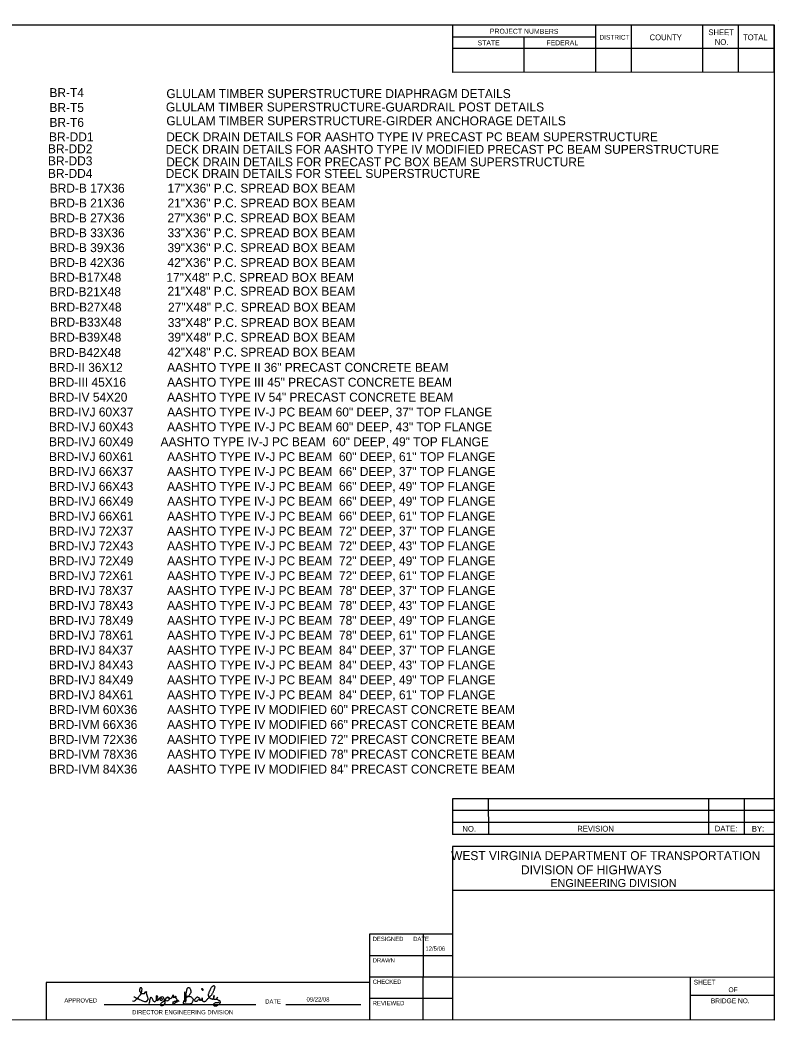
# Model space of a CAD drawing. Extents: x 4153 to 4683, y -1003 to -666.
# Drawn here: x 4427.6 to 4682.7, y -1002.2 to -666.2 of the extents above; entities that cross this region are included whole.
import ezdxf

# ---------------------------------------------------------------- set-up
doc = ezdxf.new("R2010")
doc.units = 0
for name, color, linetype in [('14', 7, 'Continuous'), ('63', 7, 'Continuous'), ('Level 1', 7, 'Continuous'), ('Level 14', 7, 'Continuous'), ('text', 7, 'Continuous')]:
    doc.layers.add(name, color=color, linetype=linetype)

msp = doc.modelspace()

# ---------------------------------------------------------------- linework, layer by layer
at = {"layer": '14'}
for p, q in [((4177.1, -667.82), (4681.11, -667.84)), ((4573.11, -683.83), (4573.11, -667.82)), ((4621.1, -683.82), (4621.11, -667.82)), ((4633.1, -683.82), (4633.11, -667.82)), ((4657.11, -683.82), (4657.11, -667.84)), ((4669.1, -683.82), (4669.11, -667.84)), ((4681.11, -667.84), (4681.1, -1002.24)), ((4681.11, -683.82), (4681.11, -667.84)), ((4621.11, -672.03), (4573.11, -672.03)), ((4597.11, -683.82), (4597.11, -672.03)), ((4681.1, -675.84), (4573.11, -675.82)), ((4681.11, -683.82), (4573.11, -683.83)), ((4681.03, -927.92), (4573.01, -927.91)), ((4573.03, -927.91), (4573.03, -939.91)), ((4585.01, -927.91), (4585.03, -939.9)), ((4659.01, -927.9), (4659.03, -939.9)), ((4671.03, -927.9), (4671.03, -939.9)), ((4681.03, -931.9), (4573.03, -931.9)), ((4681.03, -935.92), (4573.01, -935.91)), ((4681.01, -939.9), (4573.03, -939.91)), ((4573.03, -943.9), (4573.02, -1002.24)), ((4681.03, -943.92), (4573.03, -943.9)), ((4681.02, -958.73), (4573.02, -958.73)), ((4573.05, -973.43), (4545.07, -973.43)), ((4545.07, -973.43), (4545.07, -1002.23)), ((4563.07, -973.43), (4563.06, -1002.24)), ((4573.06, -980.63), (4545.06, -980.63)), ((4573.06, -987.83), (4545.06, -987.83)), ((4652.91, -987.84), (4652.91, -1002.24)), ((4681.01, -987.92), (4573.02, -987.9)), ((4681.02, -994), (4653.02, -993.98)), ((4573.05, -995.03), (4545.05, -995.03)), ((4681.1, -1002.24), (4177.07, -1002.22))]:
    msp.add_line(p, q, dxfattribs=at)
at = {"layer": '63'}
msp.add_line((4682.71, -666.24), (4682.71, -666.24), dxfattribs=at)
at = {"layer": 'Level 1'}
for p, q in [((4455.88, -997.05), (4506.84, -997.05)), ((4516.91, -997.05), (4542.21, -997.05))]:
    msp.add_line(p, q, dxfattribs=at)
for points in [[(4491.36, -994.59), (4491.46, -994.44), (4491.56, -994.29), (4491.66, -994.14), (4491.78, -994), (4491.93, -993.9), (4492.05, -993.77), (4492.15, -993.6), (4492.23, -993.43), (4492.35, -993.26), (4492.45, -993.1), (4492.52, -992.93), (4492.62, -992.74), (4492.7, -992.56), (4492.78, -992.38), (4492.85, -992.21), (4492.92, -992.04), (4492.99, -991.87), (4493.04, -991.69), (4493.1, -991.52), (4493.14, -991.34), (4493.17, -991.15), (4493.14, -990.97), (4493.02, -990.83), (4492.85, -990.77), (4492.67, -990.73), (4492.5, -990.83), (4492.35, -990.93), (4492.18, -991), (4492.05, -991.12), (4491.95, -991.27), (4491.85, -991.42), (4491.71, -991.55), (4491.68, -991.74), (4491.61, -991.91), (4491.54, -992.07), (4491.44, -992.22), (4491.38, -992.39), (4491.28, -992.54), (4491.24, -992.73), (4491.14, -992.88), (4491.11, -993.06), (4491.04, -993.25), (4490.97, -993.43), (4490.91, -993.6), (4490.91, -993.78), (4490.91, -993.97), (4490.94, -994.15), (4491.02, -994.32), (4491.09, -994.5), (4491.17, -994.67), (4491.31, -994.79), (4491.48, -994.86), (4491.63, -994.97), (4491.81, -995.01), (4491.98, -995.11), (4492.15, -995.18), (4492.35, -995.19), (4492.53, -995.19), (4492.63, -995.04), (4492.73, -994.89), (4492.82, -994.71), (4492.89, -994.52), (4492.9, -994.34), (4492.95, -994.14), (4492.82, -994.02), (4492.75, -994.2), (4492.68, -994.37), (4492.68, -994.56), (4492.68, -994.74), (4492.68, -994.92), (4492.75, -995.11), (4492.92, -995.21), (4493.09, -995.28), (4493.27, -995.29), (4493.46, -995.29), (4493.62, -995.23), (4493.72, -995.06), (4493.84, -994.92), (4493.92, -994.74), (4493.97, -994.56), (4493.89, -994.74), (4493.82, -994.91), (4493.76, -995.08), (4493.82, -995.24), (4493.99, -995.33), (4494.16, -995.41), (4494.28, -995.54), (4494.46, -995.59), (4494.65, -995.66), (4494.76, -995.8), (4494.83, -995.96), (4494.9, -996.13), (4494.9, -996.32), (4494.86, -996.5), (4494.73, -996.62), (4494.63, -996.77), (4494.49, -996.92), (4494.39, -997.07), (4494.23, -997.19), (4494.09, -997.31), (4493.92, -997.41), (4493.76, -997.51), (4493.61, -997.61), (4493.4, -997.62), (4493.22, -997.64), (4493.04, -997.64), (4492.87, -997.54), (4492.77, -997.39), (4492.73, -997.2), (4492.75, -997.02), (4492.8, -996.84), (4492.9, -996.67), (4493.02, -996.53), (4493.19, -996.47), (4493.35, -996.4), (4493.54, -996.37), (4493.72, -996.37), (4493.91, -996.33), (4494.09, -996.33), (4494.28, -996.3), (4494.46, -996.27), (4494.56, -996.23)], [(4465.46, -995.83), (4465.87, -995.9), (4466.12, -995.77), (4466.47, -995.56), (4466.74, -995.29), (4467.07, -995.09), (4467.37, -994.79), (4467.54, -994.39), (4467.78, -994.09), (4468.08, -993.82), (4468.31, -993.48), (4468.48, -993.11), (4468.55, -992.68), (4468.62, -992.27), (4468.65, -991.87), (4468.41, -991.47), (4468.04, -991.47), (4467.84, -991.77), (4467.78, -992.14), (4467.78, -992.54), (4468.04, -992.81), (4468.28, -993.15), (4468.62, -993.35), (4469.05, -993.38), (4469.42, -993.31), (4469.65, -993.01), (4469.89, -992.64), (4470.09, -992.78), (4470.02, -993.15), (4470.12, -993.52), (4470.26, -993.85), (4470.39, -994.19), (4470.46, -994.59), (4470.53, -994.99), (4470.53, -995.39), (4470.29, -995.83), (4470.02, -996.1), (4469.59, -996.1), (4469.25, -996.01), (4468.85, -995.9), (4468.51, -995.7), (4468.18, -995.61), (4467.81, -995.43), (4467.44, -995.29), (4467.14, -995.09), (4466.8, -994.96), (4466.47, -994.82), (4466.17, -994.62), (4465.83, -994.56)], [(4471.07, -996.73), (4471.17, -996.35), (4471.22, -995.98), (4471.27, -995.61), (4471.34, -995.24), (4471.47, -994.87), (4471.69, -994.57), (4471.98, -994.79), (4472.14, -995.29), (4472.21, -995.66), (4472.45, -995.93), (4472.93, -996.11), (4473.2, -995.86), (4473.44, -995.56), (4473.65, -995.28), (4473.77, -994.92), (4473.9, -994.57), (4473.85, -994.2), (4473.37, -994.14), (4473.37, -994.5), (4473.37, -994.87), (4473.42, -995.24), (4473.55, -995.59), (4473.97, -995.63), (4474.21, -995.36), (4474.32, -994.99), (4474.66, -994.84), (4475.03, -994.84), (4475.45, -995.16), (4475.33, -995.63), (4474.96, -995.66), (4474.76, -995.36), (4474.78, -994.97), (4474.89, -994.61), (4475.21, -994.44), (4475.58, -994.37), (4475.88, -994.81), (4475.98, -995.18), (4476.08, -995.53), (4476.2, -995.88), (4476.25, -996.25), (4476.25, -996.63), (4475.98, -997.09), (4475.7, -997.32), (4475.38, -997.52), (4475.01, -997.54), (4474.86, -997.04), (4474.96, -996.68), (4475.2, -996.42), (4475.45, -996.22), (4475.73, -996), (4476.19, -995.73), (4476.55, -995.34), (4476.68, -995.04), (4476.94, -994.71), (4477.16, -994.42), (4477.64, -994.52), (4477.73, -994.89), (4477.73, -995.26), (4477.59, -995.61), (4477.31, -995.83), (4476.96, -995.95), (4476.64, -995.78), (4476.57, -995.43), (4476.65, -995.08), (4476.87, -994.77), (4477.21, -994.64), (4477.69, -994.86), (4478.18, -995.02), (4478.6, -994.76), (4478.82, -994.47), (4479, -994.14), (4479.14, -993.77), (4479.14, -993.95), (4479.1, -994.32), (4479.25, -994.66), (4479.69, -994.54), (4479.92, -994.25), (4479.96, -994.27), (4479.91, -994.64), (4480.11, -994.97), (4480.38, -995.23), (4480.39, -995.59), (4480.39, -995.96), (4480.19, -996.27), (4479.92, -996.52), (4479.57, -996.67), (4479.22, -996.75), (4479, -996.47), (4479.24, -996.15), (4479.56, -995.93), (4479.92, -995.86), (4480.23, -995.66), (4480.75, -995.56), (4481.01, -995.98), (4481.05, -995.96)], [(4482.93, -992.81), (4482.94, -993), (4482.94, -993.18), (4482.94, -993.36), (4482.94, -993.57), (4482.91, -993.75), (4482.88, -993.93), (4482.88, -994.12), (4482.88, -994.3), (4482.88, -994.49), (4482.89, -994.67), (4482.91, -994.86), (4482.91, -995.04), (4482.93, -995.23), (4482.96, -995.41), (4482.98, -995.61), (4482.99, -995.8), (4483.04, -995.98), (4483.16, -996.11), (4483.26, -996.27), (4483.31, -996.08), (4483.38, -995.91), (4483.43, -995.73), (4483.45, -995.54), (4483.45, -995.36), (4483.45, -995.18), (4483.46, -994.99), (4483.46, -994.81), (4483.48, -994.62), (4483.5, -994.44), (4483.51, -994.25), (4483.51, -994.07), (4483.51, -993.88), (4483.51, -993.7), (4483.51, -993.52), (4483.51, -993.33), (4483.51, -993.15), (4483.53, -992.96), (4483.56, -992.78), (4483.6, -992.58), (4483.65, -992.39), (4483.7, -992.21), (4483.71, -992.02), (4483.78, -991.86), (4483.85, -991.69), (4483.91, -991.52), (4484.02, -991.35), (4484.18, -991.29), (4484.37, -991.3), (4484.55, -991.35), (4484.67, -991.49), (4484.75, -991.65), (4484.85, -991.81), (4484.94, -991.97), (4484.97, -992.16), (4484.99, -992.34), (4484.99, -992.53), (4484.99, -992.71), (4484.99, -992.9), (4484.99, -993.08), (4484.95, -993.26), (4484.85, -993.42), (4484.72, -993.53), (4484.6, -993.67), (4484.54, -993.83), (4484.43, -993.99), (4484.33, -994.14), (4484.27, -994.3), (4484.12, -994.4), (4483.95, -994.49), (4483.8, -994.61), (4483.63, -994.71), (4483.5, -994.82), (4483.36, -994.96), (4483.26, -995.11), (4483.13, -995.23), (4483.03, -995.38), (4482.93, -995.53), (4482.79, -995.68), (4482.69, -995.83), (4482.62, -996), (4482.52, -996.15), (4482.46, -996.32), (4482.42, -996.5), (4482.49, -996.67), (4482.66, -996.73), (4482.84, -996.75), (4483.03, -996.8), (4483.21, -996.84), (4483.4, -996.85), (4483.58, -996.85), (4483.78, -996.85), (4483.97, -996.85), (4484.15, -996.85), (4484.33, -996.85), (4484.52, -996.85), (4484.7, -996.85), (4484.89, -996.85), (4485.02, -996.72), (4485.19, -996.65), (4485.34, -996.55), (4485.49, -996.42), (4485.56, -996.25), (4485.63, -996.08), (4485.73, -995.93), (4485.79, -995.76), (4485.84, -995.58), (4485.88, -995.39), (4485.88, -995.21), (4485.76, -995.08), (4485.63, -994.96), (4485.49, -994.82), (4485.37, -994.67), (4485.21, -994.57), (4485.04, -994.47), (4484.85, -994.44), (4484.67, -994.4), (4484.48, -994.37), (4484.28, -994.37), (4484.08, -994.37), (4483.9, -994.37), (4483.71, -994.34), (4483.71, -994.34)], [(4488.68, -991.84), (4488.68, -992.02), (4488.81, -992.14), (4489, -992.19), (4489.18, -992.17), (4489.21, -991.99), (4489.08, -991.87), (4488.94, -991.74), (4488.76, -991.74), (4488.59, -991.81), (4488.59, -991.92)], [(4488.16, -995.81), (4488.19, -995.63), (4488.19, -995.44), (4488.19, -995.26), (4488.04, -995.13), (4487.91, -994.99), (4487.8, -994.84), (4487.65, -994.74), (4487.5, -994.64), (4487.34, -994.57), (4487.15, -994.57), (4486.97, -994.64), (4486.83, -994.76), (4486.68, -994.87), (4486.55, -994.99), (4486.45, -995.14), (4486.38, -995.31), (4486.28, -995.46), (4486.21, -995.63), (4486.33, -995.76), (4486.45, -995.9), (4486.65, -995.95), (4486.83, -995.95), (4487.02, -995.95), (4487.18, -995.88), (4487.3, -995.73), (4487.42, -995.59), (4487.54, -995.44), (4487.7, -995.34), (4487.91, -995.34), (4488.11, -995.36), (4488.27, -995.43), (4488.44, -995.49), (4488.59, -995.59), (4488.78, -995.59), (4488.83, -995.41), (4488.88, -995.23), (4488.89, -995.02), (4488.89, -994.84), (4488.83, -995.01), (4488.79, -995.19), (4488.79, -995.38), (4488.79, -995.56), (4488.81, -995.75), (4488.98, -995.83), (4489.15, -995.93), (4489.33, -995.98), (4489.51, -996), (4489.7, -996), (4489.88, -995.96), (4490.03, -995.86), (4490.14, -995.7), (4490.27, -995.58), (4490.37, -995.41), (4490.5, -995.29), (4490.66, -995.19), (4490.79, -995.06), (4490.92, -994.92), (4491.07, -994.82), (4491.23, -994.72), (4491.33, -994.59)]]:
    msp.add_lwpolyline(points, dxfattribs=at)
at = {"layer": 'Level 14'}
for p, q in [((4436.45, -989.61), (4436.45, -1002.23)), ((4545.07, -989.61), (4436.45, -989.61))]:
    msp.add_line(p, q, dxfattribs=at)

# ---------------------------------------------------------------- texts
at = {"layer": '14'}
for s, height, rotation, p in [('PROJECT NUMBERS', 1.6773, 359.8097, (4585.55, -670.83)), ('DISTRICT', 1.582, 359.907, (4622.39, -672.83)), ('COUNTY', 1.919, 359.9983, (4639.23, -673.02)), ('SHEET', 1.919, 359.8929, (4658.99, -671.32)), ('TOTAL', 1.919, 359.9983, (4670.62, -673.02)), ('STATE', 1.675, 0.1193, (4581.42, -674.75)), ('FEDERAL', 1.675, 359.9983, (4604.54, -674.73)), ('NO.', 1.925, 359.9983, (4661.13, -674.6)), ('NO.', 1.925, 359.9983, (4576.31, -938.97)), ('REVISION', 1.925, 359.9983, (4614.9, -938.92)), ('DATE:', 1.925, 359.9983, (4661.14, -938.88)), ('BY:', 1.925, 359.9983, (4673.59, -938.96)), (' WEST VIRGINIA DEPARTMENT OF TRANSPORTATION', 3.0011, 359.9983, (4571.41, -948.51)), ('    DIVISION OF HIGHWAYS', 3.0011, 359.9983, (4591.54, -953.28)), ('ENGINEERING DIVISION', 2.7185, 359.9983, (4605.86, -957.58)), ('DESIGNED      DATE', 1.432, 359.9983, (4546.15, -975.7)), ('12/5/06', 1.432, 359.9983, (4563.9, -978.95)), ('DRAWN', 1.432, 359.9983, (4546.15, -982.9)), ('CHECKED', 1.432, 359.9983, (4546.15, -990.1)), ('SHEET', 1.589, 359.9983, (4654.05, -990.32)), ('09/22/08', 1.432, 359.9983, (4523.93, -996.04)), ('OF', 1.604, 359.9983, (4665.73, -992.88)), ('REVIEWED', 1.447, 0.0944, (4546.16, -997.31)), ('BRIDGE NO.', 1.604, 359.9983, (4659.81, -996.6))]:
    msp.add_text(s, height=height, rotation=rotation, dxfattribs=at).set_placement(p)
at = {"layer": 'Level 14'}
for s, p in [('APPROVED', (4442.53, -996.37)), ('DATE', (4510.04, -996.73)), ('DIRECTOR ENGINEERING DIVISION', (4465.32, -1000.33))]:
    msp.add_text(s, height=1.432, rotation=359.9983, dxfattribs=at).set_placement(p)
at = {"layer": 'text'}
for s, height, p in [('BR-T4', 3.001, (4437.52, -692.14)), ('GLULAM TIMBER SUPERSTRUCTURE DIAPHRAGM DETAILS', 3.0011, (4476.82, -692.47)), ('BR-T5', 3.001, (4437.52, -697.14)), ('GLULAM TIMBER SUPERSTRUCTURE-GUARDRAIL POST DETAILS', 3.0011, (4476.66, -696.97)), ('GLULAM TIMBER SUPERSTRUCTURE-GIRDER ANCHORAGE DETAILS', 3.0011, (4476.82, -701.63)), ('BR-T6', 3.001, (4437.52, -702.14)), ('BR-DD1 ', 3.001, (4437.39, -706.97)), ('DECK DRAIN DETAILS FOR AASHTO TYPE IV PRECAST PC BEAM SUPERSTRUCTURE', 3.0011, (4476.76, -706.97)), ('BR-DD2', 3.001, (4437.02, -711.01)), ('DECK DRAIN DETAILS FOR AASHTO TYPE IV MODIFIED PRECAST PC BEAM SUPERSTRUCTURE', 3.0011, (4476.57, -711.2)), ('BR-DD3', 3.001, (4437.02, -715.06)), ('DECK DRAIN DETAILS FOR PRECAST PC BOX BEAM SUPERSTRUCTURE', 3.0011, (4476.76, -715.43)), ('BR-DD4', 3.001, (4437.02, -719.29)), ('DECK DRAIN DETAILS FOR STEEL SUPERSTRUCTURE', 3.0011, (4476.57, -719.29)), ('BRD-B 17X36', 3.0011, (4437.6, -724.23)), ('17"X36" P.C. SPREAD BOX BEAM', 3.0011, (4477.19, -724.23)), ('BRD-B 21X36', 3.0011, (4437.6, -729.23)), ('21"X36" P.C. SPREAD BOX BEAM', 3.0011, (4477.19, -729.23)), ('BRD-B 27X36', 3.0011, (4437.6, -734.23)), ('27"X36" P.C. SPREAD BOX BEAM', 3.0011, (4477.19, -734.23)), ('BRD-B 33X36', 3.0011, (4437.6, -739.23)), ('33"X36" P.C. SPREAD BOX BEAM', 3.0011, (4477.19, -739.23)), ('BRD-B 39X36', 3.0011, (4437.6, -744.23)), ('39"X36" P.C. SPREAD BOX BEAM', 3.0011, (4477.19, -744.23)), ('BRD-B 42X36', 3.0011, (4437.6, -749.23)), ('42"X36" P.C. SPREAD BOX BEAM', 3.0011, (4477.19, -749.23)), ('BRD-B17X48', 3.001, (4437.57, -754.16)), ('17"X48" P.C. SPREAD BOX BEAM', 3.0011, (4476.82, -754.21)), ('BRD-B21X48', 3.001, (4437.48, -759.03)), ('21"X48" P.C. SPREAD BOX BEAM', 3.0011, (4477.19, -758.85)), ('BRD-B27X48', 3.001, (4437.67, -764.18)), ('27"X48" P.C. SPREAD BOX BEAM', 3.0011, (4477.37, -764.21)), ('BRD-B33X48', 3.001, (4437.67, -769.24)), ('33"X48" P.C. SPREAD BOX BEAM', 3.0011, (4477.28, -769.4)), ('BRD-B39X48', 3.001, (4437.57, -774.3)), ('39"X48" P.C. SPREAD BOX BEAM', 3.0011, (4477.28, -774.31)), ('BRD-B42X48', 3.001, (4437.48, -779.45)), ('42"X48" P.C. SPREAD BOX BEAM', 3.0011, (4477.19, -779.31)), ('BRD-II 36X12', 3.0011, (4437.39, -784.45)), ('AASHTO TYPE II 36" PRECAST CONCRETE BEAM', 3.0011, (4477.07, -784.45)), ('BRD-III 45X16', 3.0011, (4437.39, -789.45)), ('AASHTO TYPE III 45" PRECAST CONCRETE BEAM', 3.0011, (4477.07, -789.45)), ('BRD-IV 54X20', 3.0011, (4437.39, -794.45)), ('AASHTO TYPE IV 54" PRECAST CONCRETE BEAM', 3.0011, (4477.07, -794.45)), ('BRD-IVJ 60X37', 3.0011, (4437.39, -799.45)), ('AASHTO TYPE IV-J PC BEAM 60" DEEP, 37" TOP FLANGE', 3.0011, (4477.07, -799.45)), ('BRD-IVJ 60X43', 3.0011, (4437.39, -804.45)), ('AASHTO TYPE IV-J PC BEAM 60" DEEP, 43" TOP FLANGE', 3.0011, (4477.07, -804.45)), ('BRD-IVJ 60X49', 3.0011, (4437.39, -809.45)), (' AASHTO TYPE IV-J PC BEAM  60" DEEP, 49" TOP FLANGE', 3.0011, (4473.74, -809.45)), ('BRD-IVJ 60X61', 3.0011, (4437.39, -814.45)), ('AASHTO TYPE IV-J PC BEAM  60" DEEP, 61" TOP FLANGE', 3.0011, (4477.07, -814.45)), ('BRD-IVJ 66X37', 3.0011, (4437.39, -819.45)), ('AASHTO TYPE IV-J PC BEAM  66" DEEP, 37" TOP FLANGE', 3.0011, (4477.07, -819.45)), ('BRD-IVJ 66X43', 3.0011, (4437.39, -824.45)), ('AASHTO TYPE IV-J PC BEAM  66" DEEP, 49" TOP FLANGE', 3.0011, (4477.07, -824.45)), ('BRD-IVJ 66X49', 3.0011, (4437.39, -829.45)), ('AASHTO TYPE IV-J PC BEAM  66" DEEP, 49" TOP FLANGE', 3.0011, (4477.07, -829.45)), ('BRD-IVJ 66X61', 3.0011, (4437.39, -834.45)), ('AASHTO TYPE IV-J PC BEAM  66" DEEP, 61" TOP FLANGE', 3.0011, (4477.07, -834.45)), ('BRD-IVJ 72X37', 3.0011, (4437.39, -839.45)), ('AASHTO TYPE IV-J PC BEAM  72" DEEP, 37" TOP FLANGE', 3.0011, (4477.07, -839.45)), ('BRD-IVJ 72X43', 3.0011, (4437.39, -844.45)), ('AASHTO TYPE IV-J PC BEAM  72" DEEP, 43" TOP FLANGE', 3.0011, (4477.07, -844.45)), ('BRD-IVJ 72X49', 3.0011, (4437.39, -849.45)), ('AASHTO TYPE IV-J PC BEAM  72" DEEP, 49" TOP FLANGE', 3.0011, (4477.07, -849.45)), ('BRD-IVJ 72X61', 3.0011, (4437.39, -854.45)), ('AASHTO TYPE IV-J PC BEAM  72" DEEP, 61" TOP FLANGE', 3.0011, (4477.07, -854.45)), ('BRD-IVJ 78X37', 3.0011, (4437.32, -859.45)), ('AASHTO TYPE IV-J PC BEAM  78" DEEP, 37" TOP FLANGE', 3.0011, (4477.07, -859.45)), ('BRD-IVJ 78X43', 3.0011, (4437.32, -864.45)), ('AASHTO TYPE IV-J PC BEAM  78" DEEP, 43" TOP FLANGE', 3.0011, (4477.07, -864.45)), ('BRD-IVJ 78X49', 3.0011, (4437.32, -869.45)), ('AASHTO TYPE IV-J PC BEAM  78" DEEP, 49" TOP FLANGE', 3.0011, (4477.07, -869.45)), ('BRD-IVJ 78X61', 3.0011, (4437.32, -874.45)), ('AASHTO TYPE IV-J PC BEAM  78" DEEP, 61" TOP FLANGE', 3.0011, (4477.07, -874.45)), ('BRD-IVJ 84X37', 3.0011, (4437.32, -879.45)), ('AASHTO TYPE IV-J PC BEAM  84" DEEP, 37" TOP FLANGE', 3.0011, (4477.07, -879.45)), ('BRD-IVJ 84X43', 3.0011, (4437.32, -884.45)), ('AASHTO TYPE IV-J PC BEAM  84" DEEP, 43" TOP FLANGE', 3.0011, (4477.07, -884.45)), ('BRD-IVJ 84X49', 3.0011, (4437.32, -889.45)), ('AASHTO TYPE IV-J PC BEAM  84" DEEP, 49" TOP FLANGE', 3.0011, (4477.07, -889.45)), ('BRD-IVJ 84X61', 3.0011, (4437.32, -894.45)), ('AASHTO TYPE IV-J PC BEAM  84" DEEP, 61" TOP FLANGE', 3.0011, (4477.07, -894.45)), ('BRD-IVM 60X36', 3.0011, (4437.39, -899.45)), ('AASHTO TYPE IV MODIFIED 60" PRECAST CONCRETE BEAM', 3.0011, (4477.07, -899.45)), ('BRD-IVM 66X36', 3.0011, (4437.39, -904.45)), ('AASHTO TYPE IV MODIFIED 66" PRECAST CONCRETE BEAM', 3.0011, (4477.07, -904.45)), ('BRD-IVM 72X36', 3.0011, (4437.39, -909.45)), ('AASHTO TYPE IV MODIFIED 72" PRECAST CONCRETE BEAM', 3.0011, (4477.07, -909.45)), ('BRD-IVM 78X36', 3.0011, (4437.39, -914.45)), ('AASHTO TYPE IV MODIFIED 78" PRECAST CONCRETE BEAM', 3.0011, (4477.07, -914.45)), ('BRD-IVM 84X36', 3.0011, (4437.39, -919.45)), ('AASHTO TYPE IV MODIFIED 84" PRECAST CONCRETE BEAM', 3.0011, (4477.07, -919.45))]:
    msp.add_text(s, height=height, dxfattribs=at).set_placement(p)

doc.saveas('drawing.dxf')
